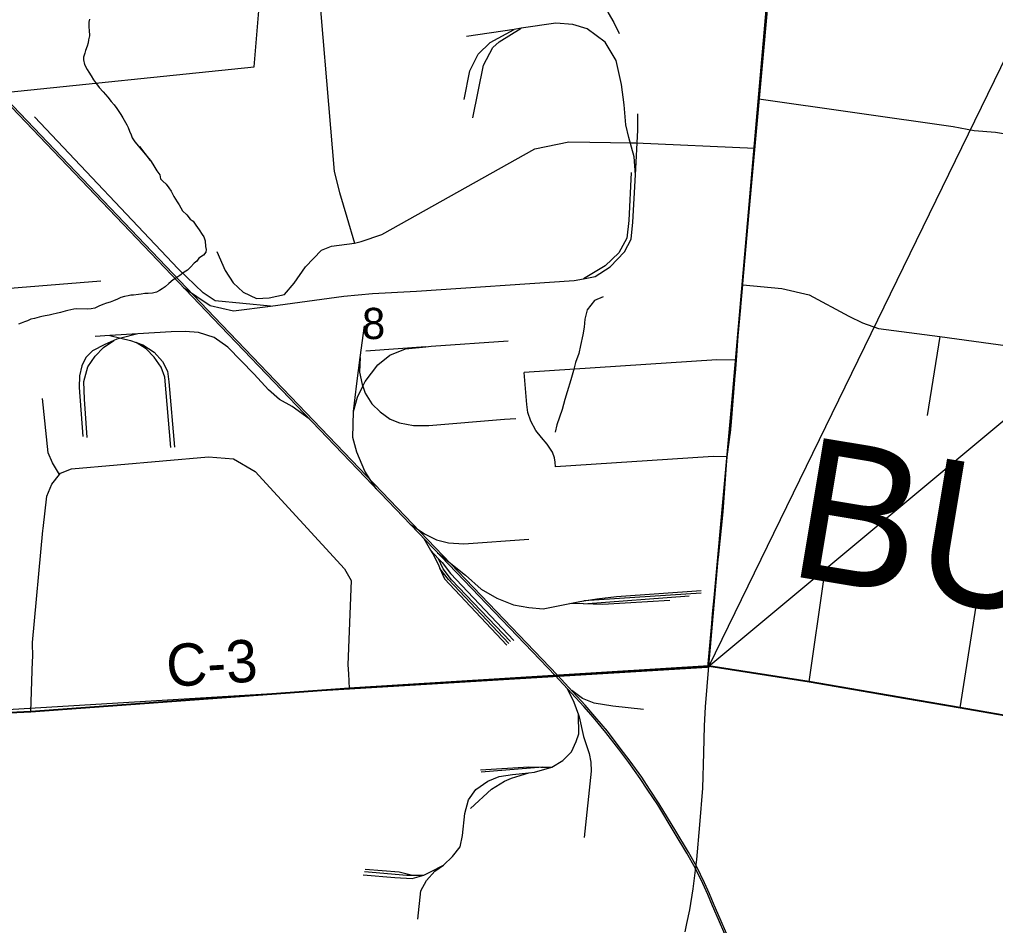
# Model space of a CAD drawing. Extents: x 0 to 34, y 0 to 22.
# Drawn here: x 3.482 to 4.792, y 15.08 to 16.296 of the extents above; entities that cross this region are included whole.
import ezdxf

# ---------------------------------------------------------------- set-up
doc = ezdxf.new("R2010")
doc.units = 0
for name, color, linetype in [('Default', 7, 'Continuous'), ('GM_X_County_Road', 7, 'Continuous'), ('GM_X_County_Road_Text', 7, 'Continuous'), ('GM_X_County_Text', 7, 'Continuous'), ('GM_X_Minor_River', 7, 'Continuous'), ('GM_X_Rail_Line', 7, 'Continuous'), ('GM_X_Section', 7, 'Continuous'), ('GM_X_Section_Text', 7, 'Continuous'), ('GM_X_State_Route', 7, 'Continuous'), ('GM_X_Township_Road', 7, 'Continuous'), ('SH_Cut_Line', 7, 'Continuous'), ('SH_Text', 7, 'Continuous')]:
    doc.layers.add(name, color=color, linetype=linetype)

msp = doc.modelspace()

# ---------------------------------------------------------------- linework, layer by layer
at = {"layer": 'Default'}
msp.add_lwpolyline([(2.8131, 18.5849), (2.7778, 18.1558), (2.5327, 18.2417), (2.4945, 17.7428), (2.4362, 17.7466), (2.1, 17.6674), (2.1, 15.6423), (2.3082, 15.6745), (2.5606, 15.599), (3.3845, 15.362), (3.4491, 16.1969), (3.7972, 16.2327), (3.8103, 16.3888), (3.7967, 16.3876), (3.8259, 16.7634), (3.5062, 16.7356), (3.5564, 17.3695), (3.6226, 18.1301), (3.6176, 18.1479), (3.628, 18.1636), (3.6366, 18.1888), (3.6479, 18.2377)], dxfattribs=at)
at = {"layer": 'GM_X_County_Road'}
for points in [[(3.3848, 15.3615), (3.4978, 15.3669), (3.9249, 15.3983), (4.4077, 15.4283)], [(4.4077, 15.4283), (4.5423, 15.407), (4.6715, 15.3848)], [(4.6715, 15.3848), (4.7449, 15.3722), (4.9349, 15.3393)]]:
    msp.add_lwpolyline(points, dxfattribs=at)
at = {"layer": 'GM_X_Minor_River'}
for points in [[(4.1298, 16.4445), (4.1379, 16.4344), (4.1411, 16.4248), (4.1502, 16.4109), (4.1635, 16.4117), (4.1757, 16.4113), (4.1893, 16.4091), (4.2006, 16.4042), (4.2114, 16.3975), (4.2248, 16.3865), (4.2381, 16.3698), (4.2431, 16.3598), (4.2501, 16.3486), (4.2548, 16.3386), (4.2617, 16.327), (4.2682, 16.3151), (4.2725, 16.3051), (4.2798, 16.2923), (4.2871, 16.2777)], [(3.5761, 16.2966), (3.5753, 16.2928), (3.5756, 16.2894), (3.5754, 16.2856), (3.5757, 16.2821), (3.5763, 16.2745), (3.575, 16.2688), (3.5745, 16.2651), (3.5732, 16.2605), (3.5711, 16.2549), (3.5699, 16.2511), (3.5682, 16.2459), (3.5681, 16.2421), (3.5694, 16.2359), (3.5734, 16.2294), (3.5756, 16.2255), (3.5785, 16.2205), (3.5818, 16.2154), (3.5858, 16.21), (3.5894, 16.2049), (3.5946, 16.1991), (3.6008, 16.192), (3.6056, 16.1862), (3.6093, 16.1819), (3.6129, 16.1768), (3.6155, 16.1729), (3.6184, 16.1687), (3.6209, 16.1644), (3.6264, 16.1551), (3.6282, 16.1513), (3.6299, 16.1463), (3.6324, 16.1413), (3.6335, 16.1374), (3.6371, 16.132), (3.658, 16.107), (3.6437, 16.126)], [(3.658, 16.107), (3.6613, 16.102), (3.6639, 16.0977), (3.6668, 16.0931), (3.6708, 16.0876), (3.6718, 16.0826), (3.6747, 16.0791), (3.6792, 16.0752), (3.6828, 16.0705), (3.6857, 16.0659), (3.6875, 16.0624), (3.6897, 16.0585), (3.6941, 16.0515), (3.6966, 16.0473), (3.6988, 16.0434), (3.7013, 16.0395), (3.7069, 16.034), (3.7112, 16.0282), (3.7154, 16.0258), (3.719, 16.0204), (3.7234, 16.0138), (3.7274, 16.0079), (3.7296, 16.0045), (3.7317, 15.9991), (3.7322, 15.9914), (3.7329, 15.9876), (3.7324, 15.9838), (3.7292, 15.9801), (3.723, 15.9761), (3.7202, 15.9717), (3.7167, 15.9691), (3.712, 15.9639), (3.7077, 15.9599), (3.7035, 15.957), (3.6976, 15.9526), (3.6922, 15.9489), (3.6887, 15.9468), (3.6829, 15.942), (3.6778, 15.9376), (3.6739, 15.9347), (3.6704, 15.9325), (3.6662, 15.9303), (3.6608, 15.929), (3.6551, 15.9284), (3.6506, 15.9285), (3.6456, 15.9276), (3.6422, 15.9273), (3.6353, 15.9264), (3.6319, 15.9261), (3.628, 15.9254), (3.6235, 15.9244), (3.6185, 15.9231), (3.6139, 15.9209), (3.6085, 15.9188), (3.6039, 15.917), (3.5993, 15.9157), (3.5943, 15.9139), (3.5889, 15.9114), (3.5835, 15.9089), (3.5785, 15.9079), (3.5736, 15.9073), (3.5587, 15.9078), (3.5553, 15.9075), (3.5511, 15.9065), (3.5473, 15.9055), (3.5438, 15.9048), (3.5373, 15.9031), (3.5316, 15.9018), (3.5274, 15.9008), (3.522, 15.8994), (3.517, 15.8984), (3.5124, 15.8974), (3.5086, 15.8968), (3.5025, 15.895), (3.4975, 15.8941), (3.4933, 15.8919), (3.4891, 15.8905), (3.4848, 15.8887), (3.481, 15.8873)], [(4.2657, 15.9239), (4.2542, 15.9192), (4.244, 15.9066), (4.2411, 15.8941), (4.24, 15.8835), (4.2382, 15.8729), (4.2352, 15.8585), (4.2331, 15.8479), (4.2286, 15.8359), (4.2257, 15.8253), (4.2223, 15.8124), (4.2174, 15.7966), (4.2144, 15.786), (4.2107, 15.7728), (4.207, 15.7626), (4.2037, 15.7521), (4.2012, 15.7423)]]:
    msp.add_lwpolyline(points, dxfattribs=at)
at = {"layer": 'GM_X_Rail_Line'}
for p, q in [((4.1463, 16.2831), (4.0823, 16.2733)), ((4.1557, 16.2845), (4.1463, 16.2831)), ((3.9395, 15.8424), (3.9453, 15.8853)), ((3.6036, 15.872), (3.5841, 15.8707)), ((3.6412, 15.8743), (3.6036, 15.872)), ((3.6036, 15.872), (3.6184, 15.8686)), ((3.6412, 15.8743), (3.6184, 15.8686)), ((4.0276, 15.8571), (3.9473, 15.8511)), ((4.0248, 15.5998), (4.0341, 15.584)), ((4.0341, 15.584), (4.0449, 15.5722)), ((4.2392, 15.512), (4.381, 15.5226)), ((4.3973, 15.526), (4.2399, 15.516)), ((4.2392, 15.512), (4.2211, 15.5125)), ((4.1847, 15.2926), (4.1021, 15.2858)), ((4.1847, 15.2926), (4.1966, 15.2928)), ((4.0096, 15.1477), (4.0252, 15.1475))]:
    msp.add_line(p, q, dxfattribs=at)
for points in [[(4.2039, 15.4164), (3.7439, 15.8967), (3.3428, 16.3169), (3.153, 16.5162), (2.8982, 16.7851), (2.7005, 16.9902), (2.596, 17.1019), (2.4324, 17.2718), (2.1, 17.6214)], [(4.2011, 15.4158), (3.7421, 15.895), (3.341, 16.3152), (3.1512, 16.5145), (2.8964, 16.7834), (2.6987, 16.9885), (2.5942, 17.1001), (2.4306, 17.27), (2.1, 17.6178)], [(4.0793, 16.189), (4.0867, 16.2275), (4.0981, 16.2497), (4.1139, 16.2655), (4.1463, 16.2831)], [(4.0907, 16.1643), (4.105, 16.2349), (4.1178, 16.2586), (4.1262, 16.2664), (4.1557, 16.2845)], [(4.3092, 16.0879), (4.3072, 16.1121), (4.3003, 16.1377), (4.2963, 16.155), (4.2939, 16.1816), (4.2904, 16.2092), (4.283, 16.2413), (4.2682, 16.2659), (4.2441, 16.2837), (4.2248, 16.2896), (4.2021, 16.2916), (4.1557, 16.2845)], [(3.8194, 15.9113), (3.7448, 15.9186), (3.7287, 15.9296), (3.6951, 15.9616), (3.5023, 16.1658)], [(4.3092, 16.0879), (4.3121, 16.1476), (4.3121, 16.1698)], [(4.3033, 16.0909), (4.3003, 16.0267), (4.2973, 16.0026), (4.2865, 15.9833), (4.2682, 15.9656), (4.2393, 15.9483)], [(4.2393, 15.9483), (4.2549, 15.9513), (4.2751, 15.9641), (4.2944, 15.9843), (4.3033, 16.0016), (4.3057, 16.0243), (4.3092, 16.0879)], [(3.8194, 15.9113), (3.9176, 15.9251), (3.956, 15.9286), (4.0152, 15.9316), (4.2268, 15.9459), (4.2393, 15.9483)], [(3.7025, 15.9365), (3.7383, 15.9125), (3.7696, 15.9054), (3.8194, 15.9113)], [(3.8713, 15.7601), (3.8485, 15.7768), (3.8314, 15.7863), (3.8167, 15.799), (3.7975, 15.82), (3.7618, 15.8564), (3.7437, 15.8693), (3.7228, 15.8763), (3.7045, 15.8774), (3.6857, 15.8772), (3.6412, 15.8743)], [(3.609, 15.8655), (3.5969, 15.8601), (3.5804, 15.8513), (3.5716, 15.8424), (3.5662, 15.8313), (3.5627, 15.8181), (3.5624, 15.8022), (3.5674, 15.7363)], [(3.5733, 15.735), (3.5695, 15.7866), (3.5687, 15.8105), (3.5741, 15.8301), (3.5839, 15.8444), (3.595, 15.8559), (3.609, 15.8655)], [(3.6184, 15.8686), (3.6128, 15.8672), (3.609, 15.8655)], [(3.6184, 15.8686), (3.6315, 15.8656), (3.6389, 15.8628)], [(3.6855, 15.7217), (3.6775, 15.8161), (3.6725, 15.8298), (3.663, 15.8431), (3.6523, 15.854), (3.6389, 15.8628)], [(3.6389, 15.8628), (3.6479, 15.8594), (3.663, 15.8499), (3.6744, 15.8373), (3.6808, 15.8243), (3.683, 15.8098), (3.6903, 15.722)], [(4.0276, 15.8571), (4.035, 15.858), (4.1384, 15.8651)], [(3.9433, 15.8039), (3.9465, 15.8104), (3.9633, 15.8326), (3.9796, 15.8459), (4.0003, 15.854), (4.0276, 15.8571)], [(3.9307, 15.7701), (3.9349, 15.8077), (3.9395, 15.8424)], [(3.9395, 15.8424), (3.9386, 15.8227), (3.9424, 15.8064), (3.9433, 15.8039)], [(3.9307, 15.7701), (3.9359, 15.7892), (3.9433, 15.8039)], [(3.9433, 15.8039), (3.9463, 15.7948), (3.9552, 15.7802), (3.9663, 15.7696), (3.9798, 15.76), (3.9924, 15.7549), (4.0113, 15.7512), (4.0316, 15.7514), (4.1334, 15.76), (4.1486, 15.7608)], [(3.9611, 15.6664), (3.9458, 15.6901), (3.9353, 15.7157), (3.9299, 15.7351), (3.9307, 15.7701)], [(4.0065, 15.6189), (4.0259, 15.6059), (4.042, 15.5976), (4.0582, 15.5936), (4.0789, 15.5926), (4.1658, 15.5988)], [(4.0341, 15.584), (4.037, 15.5791), (4.0447, 15.5643), (4.0467, 15.5594)], [(4.0433, 15.5805), (4.0809, 15.5502), (4.1021, 15.5317), (4.1231, 15.5196), (4.1453, 15.5105), (4.166, 15.5068), (4.1852, 15.5053), (4.2211, 15.5125)], [(4.1413, 15.4614), (4.0622, 15.5443), (4.0511, 15.5588), (4.0449, 15.5722)], [(4.0449, 15.5722), (4.0494, 15.5672), (4.0607, 15.5527), (4.1458, 15.4627)], [(4.1389, 15.4585), (4.058, 15.5445), (4.0467, 15.5594)], [(4.0467, 15.5594), (4.0526, 15.5455), (4.1362, 15.4565)], [(4.2399, 15.516), (4.2572, 15.5186), (4.2836, 15.5216), (4.3973, 15.5297)], [(4.2211, 15.5125), (4.2343, 15.5152), (4.2399, 15.516)], [(4.3551, 15.5162), (4.2651, 15.5112), (4.2392, 15.512)], [(4.4312, 15.0693), (4.4228, 15.089), (4.4147, 15.1075), (4.4083, 15.1226), (4.4017, 15.1374), (4.3914, 15.1588), (4.3802, 15.1787), (4.3632, 15.2066), (4.341, 15.2432), (4.3278, 15.2631), (4.3174, 15.279), (4.302, 15.3005), (4.2887, 15.3182), (4.2713, 15.3408), (4.2546, 15.3608), (4.2417, 15.3757), (4.225, 15.3936), (4.2039, 15.4164)], [(4.4289, 15.0683), (4.4205, 15.088), (4.4124, 15.1066), (4.406, 15.1216), (4.3995, 15.1364), (4.3891, 15.1577), (4.3781, 15.1774), (4.3611, 15.2053), (4.3389, 15.2419), (4.3257, 15.2617), (4.3154, 15.2776), (4.3, 15.299), (4.2868, 15.3167), (4.2693, 15.3392), (4.2527, 15.3592), (4.2399, 15.374), (4.2232, 15.3919), (4.2011, 15.4158)], [(4.2172, 15.3984), (4.2264, 15.3798), (4.2326, 15.3627)], [(4.3196, 15.3702), (4.2787, 15.3744), (4.2538, 15.3786), (4.238, 15.385), (4.2238, 15.3955)], [(4.1966, 15.2928), (4.2114, 15.3016), (4.223, 15.313), (4.2294, 15.3273), (4.2331, 15.3374), (4.2326, 15.3627)], [(4.2326, 15.3627), (4.2336, 15.3601), (4.2392, 15.3339), (4.2469, 15.3108), (4.2491, 15.2992), (4.2498, 15.2873), (4.2402, 15.1983)], [(4.1011, 15.2891), (4.166, 15.2932), (4.182, 15.2925), (4.1847, 15.2926)], [(4.166, 15.285), (4.1736, 15.2858), (4.1966, 15.2928)], [(4.0516, 15.1611), (4.0637, 15.1729), (4.074, 15.1857), (4.077, 15.2008), (4.0799, 15.2304), (4.0849, 15.2486), (4.095, 15.2627), (4.1108, 15.274), (4.126, 15.2802), (4.1438, 15.2826), (4.166, 15.285)], [(4.0878, 15.2373), (4.1159, 15.2629), (4.1334, 15.2738), (4.1426, 15.2777), (4.166, 15.285)], [(3.9465, 15.1559), (3.9919, 15.1522), (4.0096, 15.1477)], [(4.017, 15.0886), (4.021, 15.1268), (4.0286, 15.1406), (4.04, 15.1532), (4.0516, 15.1611)], [(4.0252, 15.1475), (4.0341, 15.1522), (4.0516, 15.1611)], [(3.9436, 15.1482), (3.9862, 15.1443), (4.0092, 15.1431), (4.0252, 15.1475)], [(3.9453, 15.1524), (4.002, 15.1477), (4.0096, 15.1477)]]:
    msp.add_lwpolyline(points, dxfattribs=at)
at = {"layer": 'GM_X_Section'}
msp.add_lwpolyline([(4.4981, 16.447), (4.4056, 15.4266), (3.385, 15.3645), (3.4704, 16.3589)], close=True, dxfattribs=at)
at = {"layer": 'GM_X_State_Route'}
for points in [[(4.4647, 16.0728), (4.4668, 16.0966), (4.4691, 16.1236), (4.4735, 16.1758), (4.4747, 16.1897), (4.4805, 16.2543), (4.4867, 16.3271), (4.4929, 16.4025), (4.4965, 16.4435), (4.4976, 16.484)], [(4.4504, 15.9097), (4.4504, 15.9107), (4.4531, 15.9403), (4.4532, 15.9415), (4.4602, 16.0223), (4.4644, 16.0699), (4.4647, 16.0728)], [(4.443, 15.8186), (4.4432, 15.8215), (4.4445, 15.8389), (4.447, 15.8718), (4.4504, 15.9097)], [(4.4361, 15.7392), (4.4364, 15.7413), (4.4377, 15.7562), (4.4425, 15.8126), (4.443, 15.8186)], [(4.4204, 15.5739), (4.4267, 15.6356), (4.4312, 15.6981), (4.4322, 15.7091), (4.4361, 15.7392)], [(4.4077, 15.4283), (4.4125, 15.4984), (4.4202, 15.5719), (4.4204, 15.5739)], [(4.3758, 15.0716), (4.3778, 15.0827), (4.3818, 15.1009), (4.3864, 15.1293), (4.3915, 15.1686), (4.3953, 15.215), (4.3996, 15.2643), (4.4009, 15.312), (4.4017, 15.3479), (4.403, 15.3737), (4.4077, 15.4283)]]:
    msp.add_lwpolyline(points, dxfattribs=at)
at = {"layer": 'GM_X_Township_Road'}
for p, q in [((3.4404, 15.9334), (3.5917, 15.9453)), ((4.7175, 15.8709), (4.7007, 15.7649)), ((4.5423, 15.407), (4.5624, 15.5478)), ((4.7449, 15.3722), (4.7664, 15.5087)), ((3.4978, 15.3669), (3.5, 15.4354)), ((3.9237, 15.4181), (3.9249, 15.3983))]:
    msp.add_line(p, q, dxfattribs=at)
for points in [[(3.8791, 16.3942), (3.9048, 16.0923), (3.9118, 16.0639), (3.9215, 16.031), (3.9321, 15.9959)], [(4.4747, 16.1897), (4.7352, 16.1528), (4.7634, 16.1473), (4.7924, 16.1449), (4.879, 16.1309)], [(3.7474, 15.985), (3.7584, 15.9592), (3.7692, 15.9429), (3.7825, 15.9303), (3.8005, 15.9217), (3.8175, 15.9226), (3.8378, 15.927), (3.8508, 15.9422), (3.866, 15.9644), (3.8879, 15.9868), (3.9009, 15.992), (3.9321, 15.9959), (3.9411, 15.9981), (3.9687, 16.0078), (4.1738, 16.1226), (4.2198, 16.1321), (4.3039, 16.1309)], [(4.3039, 16.1309), (4.3094, 16.1308), (4.4691, 16.1236)], [(4.4531, 15.9403), (4.5054, 15.9352), (4.5421, 15.9266), (4.5956, 15.8979), (4.6139, 15.8889), (4.6353, 15.8814), (4.7175, 15.8709), (4.8773, 15.8488)], [(4.4445, 15.8389), (4.4183, 15.8393), (4.1595, 15.8223)], [(4.4322, 15.7091), (4.4137, 15.7095), (4.4066, 15.7094), (4.2017, 15.696), (4.2012, 15.7019), (4.2005, 15.708), (4.1975, 15.7156), (4.1904, 15.7264), (4.1828, 15.7351), (4.1755, 15.7444), (4.1687, 15.757), (4.1648, 15.7686), (4.1632, 15.7794), (4.1595, 15.8223)], [(3.5361, 15.6855), (3.5265, 15.7013), (3.5207, 15.7147), (3.5133, 15.7875)], [(3.5, 15.4354), (3.5002, 15.4403), (3.5, 15.4598), (3.5139, 15.6102), (3.5142, 15.6132), (3.5191, 15.6564), (3.5257, 15.6725), (3.5361, 15.6855), (3.5376, 15.6873), (3.5522, 15.6933), (3.736, 15.7091), (3.7697, 15.7065), (3.7988, 15.6896), (3.9187, 15.5589), (3.9277, 15.5434), (3.923, 15.43), (3.9237, 15.4181)], [(2.1, 14.1), (5.2869, 14.1), (5.2994, 14.2321), (5.3008, 14.2439), (5.3077, 14.3092), (5.311, 14.341), (5.3288, 14.5334), (5.3372, 14.6237), (5.3387, 14.6408), (5.3402, 14.6549), (5.3417, 14.6691), (5.3708, 14.979), (5.3806, 15.0986), (5.3962, 15.2605), (5.26, 15.2853), (5.174, 15.2994), (5.0019, 15.3285), (4.9347, 15.3398), (4.7447, 15.3727), (4.5421, 15.4075), (4.4074, 15.4288), (3.9247, 15.3988), (3.4976, 15.3675), (3.3845, 15.362)], [(3.3845, 15.362), (3.4976, 15.3675), (3.9247, 15.3988), (4.4074, 15.4288), (4.5421, 15.4075), (4.7447, 15.3727), (4.9347, 15.3398), (5.0019, 15.3285), (5.174, 15.2994), (5.26, 15.2853), (5.3962, 15.2605), (5.5712, 15.2317), (5.7013, 15.2088), (5.759, 15.1996), (5.7963, 15.1933), (5.9659, 15.1626), (6.3032, 15.1064)]]:
    msp.add_lwpolyline(points, dxfattribs=at)
at = {"layer": 'SH_Cut_Line'}
for points in [[(3.3845, 15.362), (3.4976, 15.3675), (3.9247, 15.3988), (4.4074, 15.4288), (4.5421, 15.4075), (4.7447, 15.3727), (4.9347, 15.3398), (5.0019, 15.3285), (5.174, 15.2994), (5.26, 15.2853), (5.3962, 15.2605), (5.5712, 15.2317), (5.7013, 15.2088), (5.759, 15.1996), (5.7963, 15.1933), (5.9659, 15.1626), (6.3032, 15.1064)], [(6.3032, 15.1064), (5.9659, 15.1626), (5.7963, 15.1933), (5.759, 15.1996), (5.7013, 15.2088), (5.5712, 15.2317), (5.3962, 15.2605), (5.26, 15.2853), (5.174, 15.2994), (5.0019, 15.3285), (4.9347, 15.3398), (4.7447, 15.3727), (4.5421, 15.4075), (4.4074, 15.4288), (3.9247, 15.3988), (3.4976, 15.3675), (3.3845, 15.362)]]:
    msp.add_lwpolyline(points, dxfattribs=at)
at = {"layer": 'SH_Text'}
msp.add_lwpolyline([(4.4077, 15.4283), (4.5869, 17.4825), (4.6405, 17.7714), (4.6732, 18.1415), (4.69, 18.3364), (4.6901, 18.5827)], dxfattribs=at)
msp.add_lwpolyline([(4.8773, 16.3926), (4.4077, 15.4283), (4.8773, 15.8198)], close=True, dxfattribs=at)

# ---------------------------------------------------------------- texts
at = {"layer": 'GM_X_County_Road_Text'}
msp.add_text('C-3', height=0.05682, rotation=3.5027, dxfattribs=at).set_placement((3.681, 15.4003))
at = {"layer": 'GM_X_County_Text'}
msp.add_text('BUTLER COUNTY', height=0.189394, rotation=350.5451, dxfattribs=at).set_placement((4.5102, 15.5508))
at = {"layer": 'GM_X_Section_Text'}
msp.add_text('8', height=0.0419, rotation=0, dxfattribs=at).set_placement((3.942, 15.8673))

doc.saveas('drawing.dxf')
